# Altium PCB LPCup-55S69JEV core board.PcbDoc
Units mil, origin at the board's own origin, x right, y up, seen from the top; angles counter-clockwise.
Board outline 6000 x 4000 mil, 2 copper layers (Top Layer, Bottom Layer); 53 components, 52 nets, 231 pads, 94 vias.
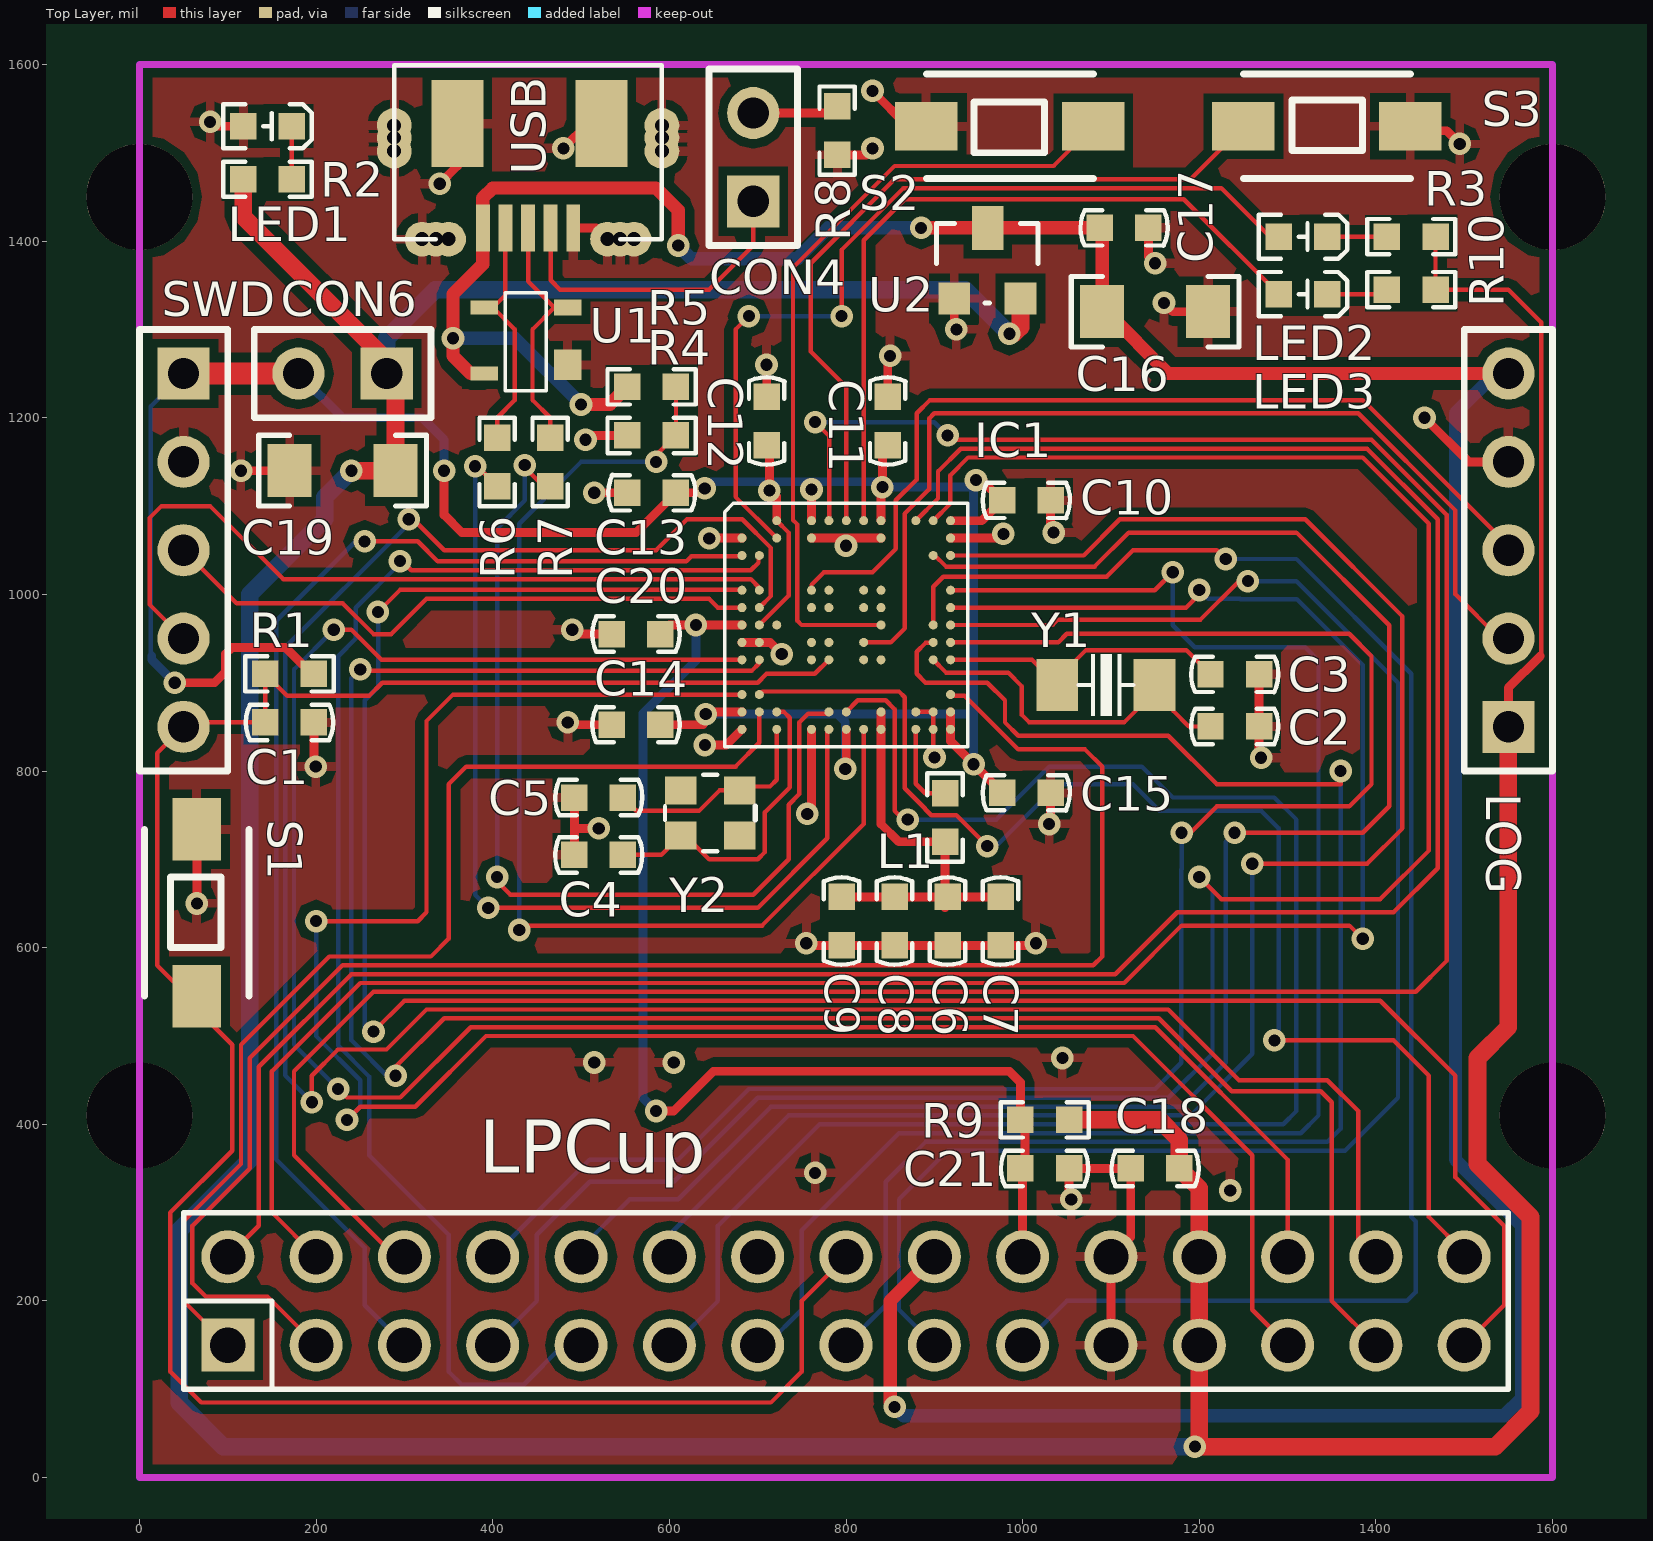
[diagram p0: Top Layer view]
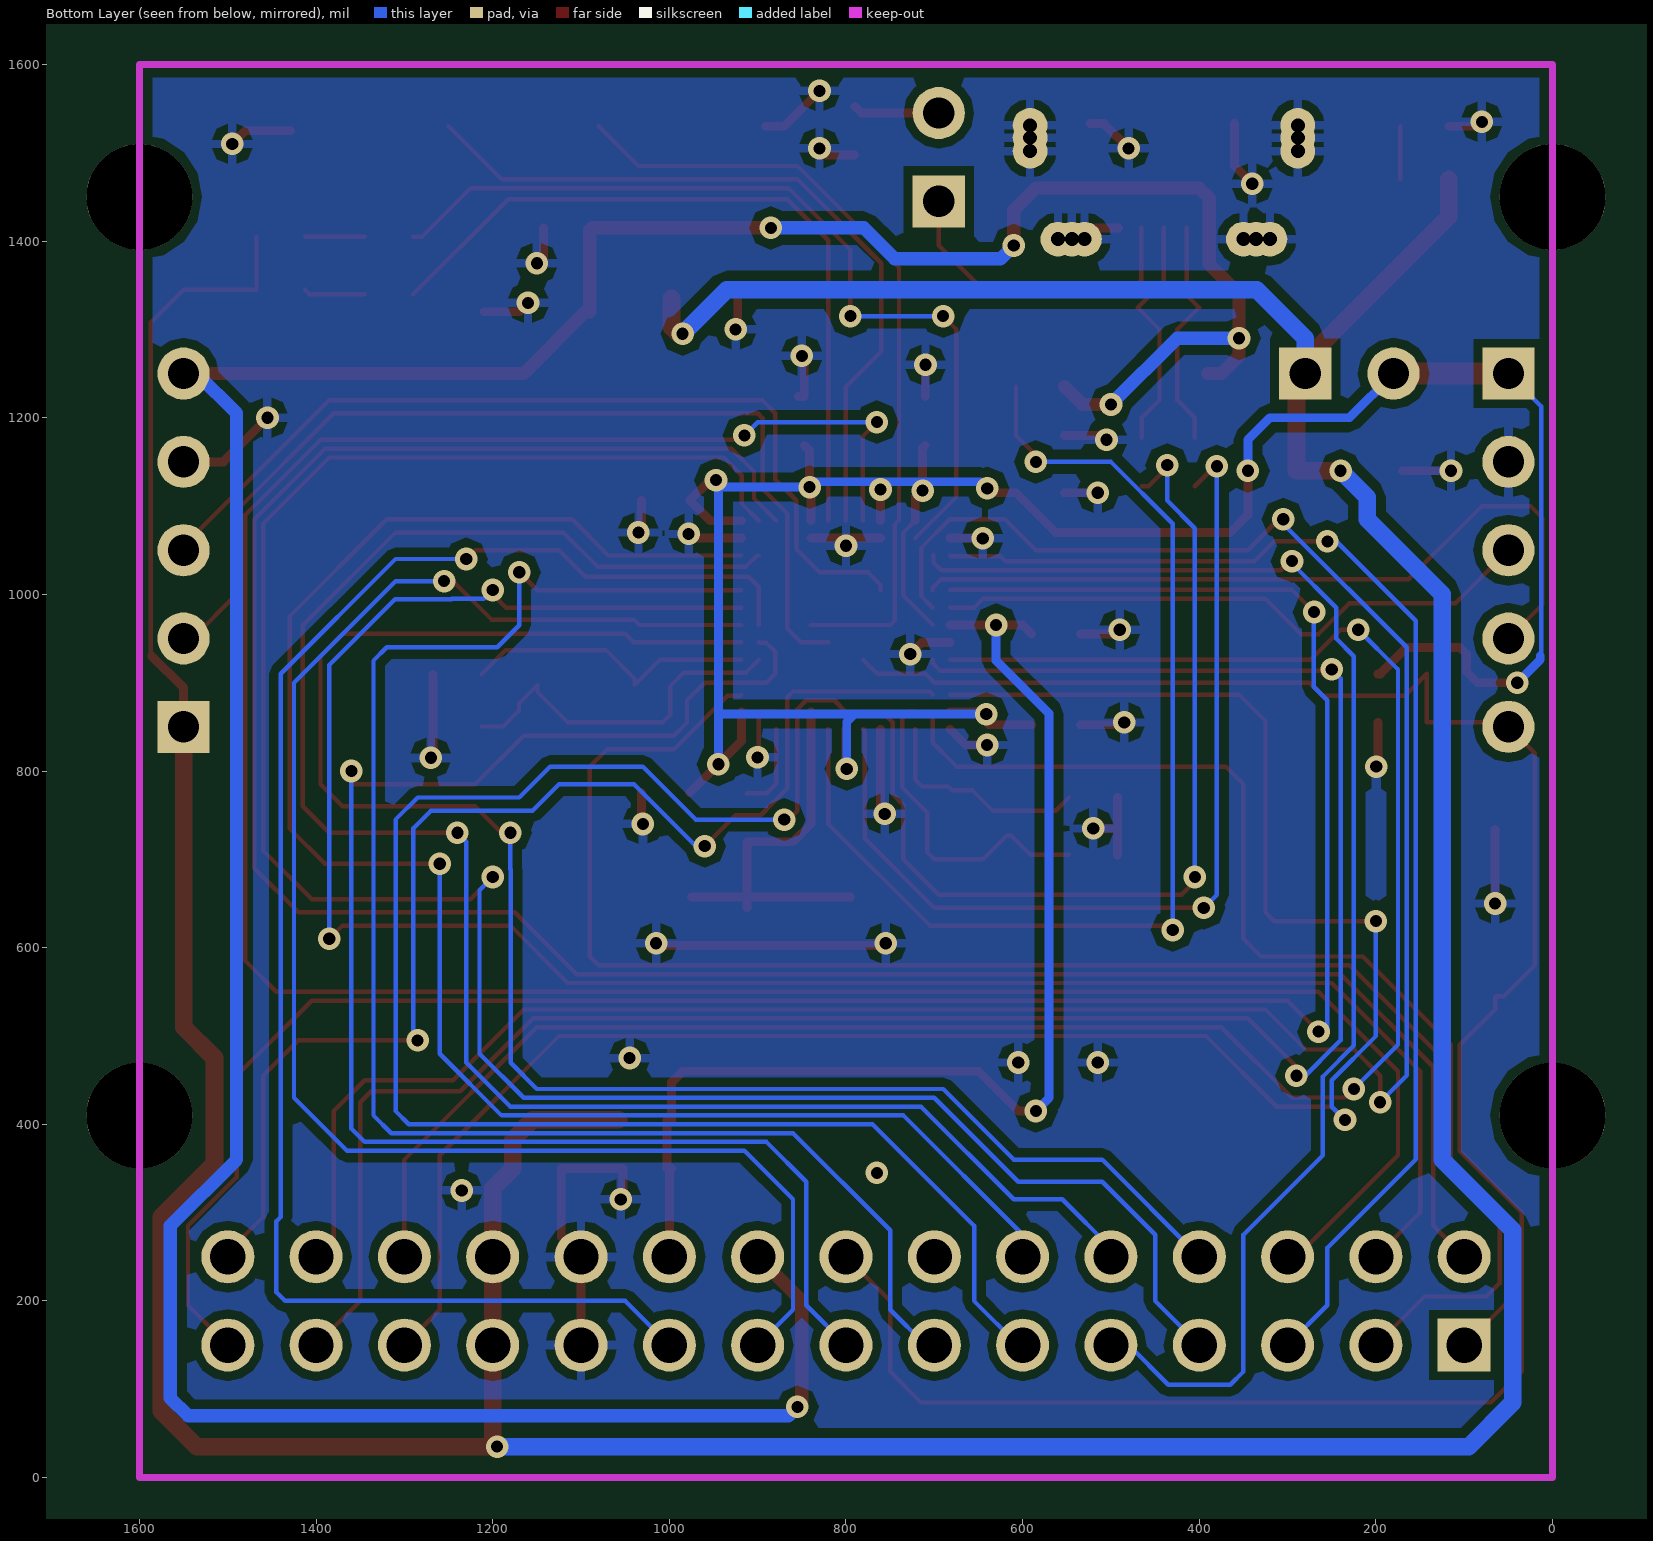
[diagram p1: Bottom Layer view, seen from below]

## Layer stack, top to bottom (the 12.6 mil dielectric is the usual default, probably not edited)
Top Solder: solder mask 0.4, Solder Resist, Dk 3.5
Top Layer: signal copper 1.4
Dielectric1: dielectric 12.6, FR-4, Dk 4.8
Bottom Layer: signal copper 1.4
Bottom Solder: solder mask 0.4, Solder Resist, Dk 3.5

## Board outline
-1716.54,-1216.54 4283.46,-1216.54 4283.46,2783.46 -1716.54,2783.46

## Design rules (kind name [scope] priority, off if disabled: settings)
Clearance [All] p1: gap=5
MinimumSolderMaskSliver [All] p1: minsoldermaskwidth=2
PolygonConnect [All] p1: connectstyle=Relief reliefconductorwidth=10 reliefentries=4 polygonreliefangle="90 Angle" airgapwidth=10
RoutingVias [All] p1: holewidth=13.78 width=25.59 viastyle="Through Hole" minholewidth=13.78 minwidth=25.59 maxholewidth=13.78 maxwidth=25.59
SilkToSolderMaskClearance SilkscreenOverComponentPads [IsPad] p1: minsilkscreentomaskgap=10 clearancetoexposedcopper=TRUE
SolderMaskExpansion [All] p1: expansion=3
Width [All] p1: maxlimit=50 minlimit=5 preferedwidth=8 minimp=50.000000 maximp=50.000000 favimp=50.000000
27 further rules are at their usual default settings.

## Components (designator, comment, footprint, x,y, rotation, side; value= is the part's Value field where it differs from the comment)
C1 "0.1uF" C0603 170,855 r180 top
C2 "0.1uF" C0603 1240.2,850.42 r180 top
C3 "0.1uF" C0603 1240.2,909.42 r180 top
C4 "0.1uF" C0603 520,705 r0 top
C5 "0.1uF" C0603 520,770 r0 top
C6 "2.2uF" C0603 915,630 r90 top
C7 "100nF" C0603 975,630 r90 top
C8 "47pF" C0603 855,630 r90 top
C9 "22uF" C0603 795,630 r90 top
C10 "0.1uF" C0603 1004.2,1106.42 r180 top
C11 "0.1uF" C0603 847.2,1196.42 r270 top
C12 "0.1uF" C0603 710.2,1196.42 r270 top
C13 "0.1uF" C0603 580,1115 r0 top
C14 "0.1uF" C0603 562.2,852.42 r0 top
C15 "0.1uF" C0603 1004.2,775.42 r180 top
C16 "10uF" C1206 1150,1320 r180 top
C17 "0.1uF" C0603 1115,1415 r180 top
C18 "0.1uF" C0603 1150,350 r0 top
C19 "10uF" C1206 230,1140 r0 top
C20 "0.1uF" C0603 562.2,955 r0 top
C21 "0.1uF" C0603 1025,350 r180 top
CON4 "SIP2" SIP2_2.54 695,1445 r90 top
CON6 "CON2" SIP2_2.54 280,1250 r180 top
IC1 "LPC55S69JEV98" VFBGA98_SIMPLE 682.2,1083.42 r0 top
L1 "48uH" L0603 912.2,747.42 r270 top
LED1 "LED" LED0603 145,1530 r0 top
LED2 "LED" LED0603 1317.5,1405 r0 top
LED3 "LED" LED0603 1317.5,1340 r0 top
LOG "SIP5" SIP5_2.54 1550,850 r90 top (schematic designator CON2)
LPCup "LPCUP" LPCUP 100,150 r90 top (schematic designator CON1)
R1 "10k" R0603 170,910 r0 top
R2 "4.7K" R0603 145,1470 r180 top
R3 "4.7K" R0603 1440,1405 r0 top
R4 "20K" R0603 580,1180 r0 top
R5 "10K" R0603 580,1235 r180 top
R6 "33R" R0603 405,1150 r90 top
R7 "33R" R0603 465,1150 r90 top
R8 "10K" R0603 790,1525 r90 top
R9 "0R" R0603 1025,405 r0 top
R10 "4.7K" R0603 1440,1345 r0 top
S1 "KEY" SW2P_4X6_SMD 65,545 r90 top
S2 "KEY" SW2P_4X6_SMD 1250,1530 r0 top
S3 "KEY" SW2P_4X6_SMD 1080,1530 r180 top
SWD "SIP5" SIP5_2.54 50,1250 r270 top (schematic designator CON5)
U1 "PRTR5V0U2X" SOT143B 485,1250 r180 top
U2 "HT7233" SOT23-3 960,1375 r270 top
USB "MicroUSB" MicroUSB 440,1415 r0 top (schematic designator CON3)
Y1 "32.768kHz" SMD3215_2P 1094.2,897.42 r180 top
Y2 "16.00MHz" SMD3225_4P 646.2,752.42 r0 top
? "Comment" FOOTPAD2#1 -170,590 r0 top
? "Comment" FOOTPAD2#2 165,590 r0 top
? "Comment" FOOTPAD2#3 1605,1220 r0 top
? "Comment" FOOTPAD2#4 135,1245 r0 top

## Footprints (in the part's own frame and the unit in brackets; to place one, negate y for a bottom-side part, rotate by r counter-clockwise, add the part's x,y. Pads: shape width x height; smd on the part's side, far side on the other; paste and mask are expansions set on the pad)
C0603 [mil]
  rect 30x30 smd: 1(27.5,0) 2(-27.5,0)
  silkscreen extent -49,-20 50,20
C1206 [mil]
  rect 50x60 smd: 1(60,0) 2(-60,0)
  silkscreen extent -95,-40 95,40
FOOTPAD2#1 [mil]
  round 120 hole 120 unplated: 0(170,-180)
FOOTPAD2#2 [mil]
  round 120 hole 120 unplated: 0(1435,-180)
FOOTPAD2#3 [mil]
  round 120 hole 120 unplated: 0(-5,230)
FOOTPAD2#4 [mil]
  round 120 hole 120 unplated: 0(-135,205)
L0603 [mil]
  rect 30x30 smd: 1(27.5,0) 2(-27.5,0)
  silkscreen extent -50,-20 50,20
LED0603 [mil]
  rect 30x30 smd: 1(27.5,0) 2(-27.5,0)
  silkscreen extent -50,-25 50,25
LPCUP [mil]
  rect 60x60 hole 40: 1(0,0)
  round 60 hole 40: 2(0,-100) 3(0,-200) 4(0,-300) 5(0,-400) 6(0,-500) 7(0,-600) 8(0,-700) 9(0,-800) 10(0,-900) 11(0,-1000) 12(0,-1100) 13(0,-1200) 14(0,-1300) 15(0,-1400) 16(100,0) 17(100,-100) 18(100,-200) 19(100,-300) 20(100,-400) 21(100,-500) 22(100,-600) 23(100,-700) 24(100,-800) 25(100,-900) 26(100,-1000) 27(100,-1100) 28(100,-1200) 29(100,-1300) 30(100,-1400)
  silkscreen extent -50,-1450 150,50
MicroUSB [mm]
  round 1 hole 0.4: 0(-3.85,2.206) 0(-3.85,2.591) 0(-3.85,2.946) 0(-3.048,-0.325) 0(-2.65,-0.325) 0(-2.286,-0.325) 0(2.286,-0.325) 0(2.65,-0.325) 0(3.048,-0.325) 0(3.85,2.206) 0(3.85,2.591) 0(3.85,2.946)
  rect 1.5x2.5 smd: 0(-2.032,2.997) 0(2.108,2.997)
  rect 0.4x1.35 smd: 1(-1.3,0) 2(-0.65,0) 3(0,0) 4(0.65,0) 5(1.3,0)
  silkscreen extent -3.85,-0.32 3.85,4.68
R0603 [mil]
  rect 30x30 smd: 1(27.5,0) 2(-27.5,0)
  silkscreen extent -50,-20 50,20
SIP2_2.54 [mm] "Connector; Header; 5 Position"
  rect 1.5x1.5 hole 0.9: 1(0,0)
  round 1.5 hole 0.9: 2(2.54,0)
  silkscreen extent -1.27,-1.27 3.81,1.27
SIP5_2.54 [mm] "Connector; Header; 5 Position"
  rect 1.5x1.5 hole 0.9: 1(0,0)
  round 1.5 hole 0.9: 2(2.54,0) 3(5.08,0) 4(7.62,0) 5(10.16,0)
  silkscreen extent -1.27,-1.27 11.43,1.27
SMD3215_2P [mm]
  rect 1.2x1.5 smd: 1(-1.4,0) 2(1.4,0)
  silkscreen extent -0.79,-0.89 0.79,0.89
SMD3225_4P [mm]
  rect 0.9x0.8 smd mask-0.051: 1(-0.85,-0.65) 2(0.85,-0.65) 3(0.85,0.65) 4(-0.85,0.65)
  silkscreen extent -1.3,-1.1 1.3,1.1
SOT23-3 [mil]
  rect 36x36 smd: 1(40,-37.5) 2(40,37.5)
  rect 50x36 smd: 3(-40,0.5)
  silkscreen extent -45,-58 45,58
SOT143B [mm]
  rect 0.8x0.88 smd: 1(0,-0.25)
  rect 0.8x0.45 smd: 2(0,-1.9)
  rect 0.8x0.4 smd: 3(2.4,-1.9) 4(2.4,0)
  silkscreen extent 0.63,-2.32 1.8,0.5
SW2P_4X6_SMD [mm]
  rect 1.8x1.4 smd: 1(0,0) 2(4.8,0)
  silkscreen extent 0,-1.5 4.8,1.5
VFBGA98_SIMPLE [mm]
  round 0.26 smd: A3(1,0) A5(2,0) A6(2.5,0) A7(3,0) A8(3.5,0) A9(4,0) A11(5,0) A12(5.5,0) A13(6,0) B1(0,-0.5) B3(1,-0.5) B5(2,-0.5) B9(4,-0.5) B13(6,-0.5) C1(0,-1) C2(0.5,-1) C12(5.5,-1) C13(6,-1) E1(0,-2) E2(0.5,-2) E5(2,-2) E6(2.5,-2) E8(3.5,-2) E9(4,-2) E13(6,-2) F1(0,-2.5) F2(0.5,-2.5) F5(2,-2.5) F6(2.5,-2.5) F8(3.5,-2.5) F9(4,-2.5) F13(6,-2.5) G1(0,-3) G2(0.5,-3) G3(1,-3) G9(4,-3) G12(5.5,-3) G13(6,-3) H1(0,-3.5) H2(0.5,-3.5) H5(2,-3.5) H6(2.5,-3.5) H8(3.5,-3.5) H12(5.5,-3.5) H13(6,-3.5) J1(0,-4) J2(0.5,-4) J5(2,-4) J6(2.5,-4) J8(3.5,-4) J9(4,-4) J12(5.5,-4) J13(6,-4) L1(0,-5) L2(0.5,-5) L13(6,-5) M1(0,-5.5) M2(0.5,-5.5) M3(1,-5.5) M6(2.5,-5.5) M7(3,-5.5) M9(4,-5.5) M11(5,-5.5) M12(5.5,-5.5) M13(6,-5.5) N1(0,-6) N3(1,-6) N5(2,-6) N6(2.5,-6) N7(3,-6) N8(3.5,-6) N9(4,-6) N11(5,-6) N12(5.5,-6) N13(6,-6)
  silkscreen extent -0.5,-6.5 6.5,0.5

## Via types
v1: diameter 25.59, hole 13.78, Top Layer to Bottom Layer, 94 vias

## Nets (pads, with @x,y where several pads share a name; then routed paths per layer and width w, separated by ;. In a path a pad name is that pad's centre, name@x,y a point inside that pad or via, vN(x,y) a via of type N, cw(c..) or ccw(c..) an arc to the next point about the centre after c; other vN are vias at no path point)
ADC0_0: IC1.J1 LPCup.28 | length 2319.8
  Top Layer w5: v1(220,960) 240,960 274.05,925.94 IC1.J1 ; v1(225,440) 234.7,430.3 295.3,430.3 375,510 1150,510 1300,360 LPCup.28
  Bottom Layer w5: v1(220,960) 175,915 175,490 v1(225,440)
ADC0_1: IC1.F2 LPCup.29 | length 2723
  Top Layer w5: v1(195.3,425) 195,425.3 195,455 224.7,484.7 279.7,484.7 325,530 1165,530 1245,450 1345,450 1380,415 1380,270 LPCup.29 ; v1(305,1085) 310,1085 345,1050 585,1050 620,1085 682.47,1085 715,1052.47 715,998.11 IC1.F2
  Bottom Layer w5: v1(195.3,425) 165,455.3 165,940 300,1075 300,1080 v1(305,1085)
ADC0_2: IC1.L2 LPCup.30 | length 1427.5
  Top Layer w5: IC1.L2 705.31,890 860,890 866.44,883.56 866.44,780.49 889.7,757.22 889.7,756.82 896.52,750 925,750 v1(960,715) ; v1(1285,495) 1420,495 1460,455 1460,295 1500,255 LPCup.30
  Bottom Layer w5: v1(960,715) 970,715 1040,785 1125,785 1155,755 1270,755 1290,735 1290,500 v1(1285,495)
ADC0_3: IC1.L1 LPCup.13 | length 2319.1
  Top Layer w5: v1(200,630) 315,630 325,640 325,856.57 355,886.57 IC1.L1 ; v1(235,405) 250,420 312.43,420 392.43,500 1125,500 1260,365 1260,190 LPCup.13
  Bottom Layer w5: v1(200,630) 200,500 250,450 250,420 v1(235,405)
ADC0_8: IC1.J2 LPCup.14 | length 2382.8
  Top Layer w5: v1(250,915) 251.67,913.33 693.11,913.33 701.89,922.11 IC1.J2 ; v1(290,455) 290,465 345,520 1154.14,520 1236.64,437.5 1337.5,437.5 1350,425 1350,200 LPCup.14
  Bottom Layer w5: v1(250,915) 240,905 240,495 285,450 v1(290,455)
ADC0_11: IC1.E1 LPCup.15 | length 2535.3
  Top Layer w5: v1(265,505) 300,540 1405,540 1490,455 1490,340 1545,285 1545,195 LPCup.15 ; v1(270,980) 295,1005 681.89,1005 IC1.E1
  Bottom Layer w5: v1(265,505) 255,505 255,880 270.3,895.3 270.3,979.7 v1(270,980)
GND: C1.2 C2.2 C3.2 C4.2 C5.2 C6.2 C7.2 C8.2 C9.2 C10.2 C11.2 C12.2 C13.2 C14.2 C15.2 C16.2 C17.2 C18.2 C19.2 C20.2 C21.2 IC1.B1 IC1.B5 IC1.B9 IC1.B13 IC1.H1 IC1.H2 IC1.M11 IC1.M12 IC1.N1 IC1.N5 IC1.N12 LED1.2 LOG.4 LPCup.11 LPCup.26 R4.2 R8.2 S1.2 S2.2 S3.2 SWD.2 U1.1 U2.1 USB.0 USB.5 | length 2425.9
  Top Layer w5: IC1.M11 IC1.M12 IC1.N12 898.74,824.89 904.2,819.42 v1(900.2,815.42)
  Top Layer w10: v1(65,650) S1.2 ; v1(80,1535) 85,1530 LED1.2 ; v1(115,1140) C19.2 ; C1.2 197.5,807.2 v1(199.7,805) ; v1(340,1465) 360,1485 USB.0@360,1533 ; v1(480,1505) 508,1533 USB.0@523,1533 ; v1(485,855) 487.57,852.42 C14.2 ; v1(490,960) 495,955 C20.2 ; USB.5 517.21,1415 USB.0@530,1402.21 ; C4.2 492.5,735 ; C5.2 492.5,735 ; v1(505,1175) 510,1180 R4.2 ; v1(515,1115) C13.2 ; v1(520,735) 492.5,735 ; v1(640.2,829.42) 664.42,829.42 IC1.N1 ; v1(645.2,1063.42) 645.52,1063.74 IC1.B1 ; IC1.H1 IC1.H2 714,945.63 v1(727.2,932.42) ; v1(710,1260) 710.2,1259.79 C12.2 ; v1(755,605) 757.5,602.5 C9.2 C8.2 C6.2 C7.2 1012.5,602.5 v1(1015,605) ; v1(756.2,751.42) 760.94,756.16 IC1.N5 ; IC1.B5 v1@800,1063.74 ; R8.2 822.5,1497.5 v1(830,1505) ; v1(800,1055) v1@800,1063.74 ; v1(830,1570) 870,1530 S3.2 ; IC1.B9 v1@800,1063.74 ; v1(850,1270) 847.2,1267.2 C11.2 C11.2@853.92,1223.92 ; IC1.B13 973.52,1063.74 v1(978.2,1068.42) ; U2.1 922.5,1302.5 v1(925,1300) ; v1(1030,740) 1031.7,741.7 C15.2 ; C10.2 1031.7,1066.7 v1(1035,1070) ; v1(1055,315) 1052.5,317.5 C21.2 C18.2 1122.5,272.5 LPCup.26 LPCup.11 ; C17.2 1142.5,1382.5 v1(1150,1375) ; v1(1160,1330) 1170,1320 C16.2 ; C3.2 C2.2 1267.7,817.29 v1(1270,815) ; S2.2@1428.98,1525 1480,1525 v1(1495,1510) ; v1(1455,1200) 1505,1150 LOG.4
  other v1: 1235,325 765,345 515,470 605,470 1045,475
HSSPI_MISO: IC1.G13 LPCup.9 | length 1839
  Top Layer w5: IC1.G13 1033.89,965.31 1040,971.42 1201.42,971.42 1245,1015 v1(1255,1015)
  Bottom Layer w5: LPCup.9 860,190 860,315 915,370 1365,370 1425,430 1425,900 1310,1015 v1(1255,1015)
HSSPI_MOSI: IC1.H12 LPCup.8 | length 1758.1
  Top Layer w5: IC1.H12 898.11,945 890,945 880,935 880,910 890,900 960,900 980,880 980,855 995,840 1165,840 1220,785 1360,785 v1(1360,800)
  Bottom Layer w5: LPCup.8 845,195 845,335 890,380 1345,380 1360,395 v1(1360,800)
HSSPI_SCK: IC1.G12 LPCup.10 | length 1831.7
  Top Layer w5: IC1.G12 898.74,1008.74 910,1020 1095,1020 1125,1050 1220,1050 v1(1230,1040)
  Bottom Layer w5: LPCup.10 1050,200 1435,200 1445,210 1445,290 1440,295 1440,448.75 1440,756.25 1440,910 1310,1040 v1(1230,1040)
HSSPI_SSEL: IC1.E13 LPCup.7 | length 1812
  Top Layer w5: IC1.E13 1149.68,1004.68 v1(1170,1025)
  Bottom Layer w5: LPCup.7 710,150 750,190 750,280 860,390 1315,390 1335,410 1335,925 1320,940 1195,940 1170,965 v1(1170,1025)
I2C1_SCL: IC1.C13 LPCup.21 | length 1985.6
  Top Layer w5: IC1.C13 1069.05,1044.05 1110,1085 1320,1085 1430,975 1430,735 1390,695 v1(1260,695)
  Bottom Layer w5: LPCup.21 600,275 735,410 1190,410 1260,480 v1(1260,695)
I2C1_SDA: IC1.C12 LPCup.20 | length 2064.5
  Top Layer w5: IC1.C12 900.58,1044.05 913.2,1031.44 1081.44,1031.44 1120,1070 1310,1070 1415,965 1415,760 1385,730 v1(1240,730)
  Bottom Layer w5: LPCup.20 500,260 555,315 610,315 715,420 1180,420 1230,470 1230,720 v1(1240,730)
MCU_RESET: C1.1 IC1.J6 LPCup.23 R1.2 S1.1 SWD.5 | length 2522.2
  Top Layer w5: IC1.J6 764.68,910 710,910 700,900 275,900 260,885 167.5,885 R1.2 C1.1 55,855 SWD.5 20,820 20,580 55,545 S1.1 65,530 105,490 105,370 35,300 35,120 70,85 715,85 750,120 750,200 LPCup.23
MCU_SWCLK: IC1.F1 SWD.3 | length 692.3
  Top Layer w5: SWD.3 110,990 230,990 265,955 285,955 325,995 645,995 655,985 IC1.F1
MCU_SWDIO: IC1.E2 SWD.4 | length 889.6
  Top Layer w5: SWD.4 11.5,988.5 11.5,1086.5 25,1100 80,1100 162.7,1017.3 692.2,1017.3 701.89,1007.62 IC1.E2
N16082712: IC1.N11 L1.2 | length 99.2
  Top Layer w5: IC1.N11 879.05,785.57 889.7,774.92 L1.2
N16082716: C6.1 C7.1 C8.1 C9.1 IC1.M9 IC1.N9 L1.1 | length 466.3
  Top Layer w10: C9.1 C8.1 C6.1 ; IC1.M9 IC1.N9 839.68,739.94 859.7,719.92 L1.1 C6.1@912.2,645.29 ; C6.1@912.2,660.29 C6.1 ; C7.1 C6.1
N16083730: C4.1 IC1.M3 Y2.1 | length 365.4
  Top Layer w5: C4.1 590.91,705 Y2.1 618.17,726.83 645,700 700,700 708.2,708.2 708.2,753.42 736.2,781.42 736.2,860.42 729.74,866.89 IC1.M3
N16083734: C5.1 IC1.N3 Y2.3 | length 252.2
  Top Layer w5: C5.1 562.5,755 591.68,755 591.92,754.77 633.56,754.77 656.81,778.02 Y2.3 684.08,782.42 713.94,782.42 721.57,790.05 IC1.N3
N16083761: C2.1 IC1.J12 Y1.1 | length 408.4
  Top Layer w5: IC1.J12 913.26,911.42 983.57,911.42 999.2,895.79 999.2,863.42 1007.2,855.42 1115.2,855.42 1149.32,889.54 Y1.1 1170.2,876.54 1170.2,868.42 1188.2,850.42 C2.1
N16083765: C3.1 IC1.J13 Y1.2 | length 337.9
  Top Layer w5: IC1.J13 1010.57,925.94 Y1.2 1039.09,904.31 1071.7,936.92 1185.2,936.92 C3.1
N16094991: R6.1 U1.3 USB.2 | length 261.9
  Top Layer w5: R6.1 405,1200 425,1220 425,1300 400.2,1324.8 414.41,1339.02 USB.2
N16095091: R7.1 U1.2 USB.3 | length 268.4
  Top Layer w5: USB.3 440,1354.61 469.8,1324.8 445,1300 445,1220 465,1200 R7.1
N16095095: CON4.1 USB.4 | length 363.9
  Top Layer w5: USB.4 465.59,1355.57 476.16,1345 645,1345 695,1395 CON4.1
N16095123: CON4.2 R8.1 | length 98.1
  Top Layer w10: CON4.2 782.5,1545 R8.1
N160852890: LED1.1 R2.2 | length 60
  Top Layer w5: R2.2 LED1.1
N161073140: LED2.1 R3.2 | length 67.5
  Top Layer w5: LED2.1 R3.2
N161283560: LED3.1 R10.2 | length 69.6
  Top Layer w5: LED3.1 1407.5,1340 R10.2
PIO0_05/ISP: IC1.A7 S2.1 | length 862.5
  Top Layer w5: IC1.A7 800.31,1234.68 760,1275 760,1375 855,1470 1190,1470 S2.1
PIO0_21/D3: IC1.A12 LPCup.4 | length 2505.8
  Top Layer w5: IC1.A12 918.2,1102.89 918.2,1135 938.2,1155 1385,1155 1460,1080 1460,710 1405,655 1225,655 v1(1200,680)
  Bottom Layer w5: LPCup.4 450,200 450,275 510,335 605,335 700,430 1165,430 1215,480 1215,665 v1(1200,680)
PIO0_25/D4: IC1.A11 LPCup.16 | length 2728.5
  Top Layer w5: LPCup.16 135,285 135,465 240,570 1105,570 1175,640 1420,640 1470,690 1470,1085 1390,1165 930,1165 904.2,1139.2 904.2,1108.57 IC1.A11
PIO0_28/D5: IC1.F13 LPCup.17 | length 2363.3
  Top Layer w5: LPCup.17 150,300 150,460 250,560 1115,560 1180,625 1370,625 v1(1385,610) ; IC1.F13 1185,985 1200,1000 v1(1200,1005)
  Bottom Layer w5: v1(1200,1005) 1210,995 1246.3,995 1246.59,994.7 1310.3,994.7 1385,920 v1(1385,610)
PIO1_08/D6: IC1.A6 LPCup.18 | length 3009.4
  Top Layer w5: LPCup.18 290,250 175,365 175,460 265,550 1445,550 1480,585 1480,1090 1395,1175 915,1175 v1(915,1180) ; v1(765,1195) 781.24,1178.76 781.24,1084.04 IC1.A6
  Bottom Layer w5: v1(765,1195) 900,1195 v1(915,1180)
PIO1_09/D2: IC1.C1 LPCup.3 | length 1457
  Top Layer w5: v1(255,1060) 315,1060 337.7,1037.3 619.17,1037.3 625,1043.13 681.28,1043.13 IC1.C1
  Bottom Layer w5: v1(255,1060) 245,1060 155,970 155,950 154.7,949.7 154.7,360.3 255,260 255,195 LPCup.3
PIO1_13/LEDG: IC1.B3 LED2.2 | length 1003.5
  Top Layer w5: v1(690,1315) 675,1300 675,1110.31 IC1.B3 ; v1(795,1315) 795,1390 865,1460 1225,1460 1280,1405 LED2.2
  Bottom Layer w5: v1(690,1315) v1(795,1315)
PIO1_18/WAKEUP: IC1.G9 S3.1 | length 905
  Top Layer w5: IC1.G9 749.68,965.31 745,970 745,1079.14 740,1084.14 740,1370 855,1485 1035,1485 S3.1
PIO1_19/D7: IC1.H13 LPCup.19 | length 2005
  Top Layer w5: IC1.H13 1040.31,945.63 1050,955.31 1369.68,955.31 1395,930 1395,785 1370,760 1220,760 1190,730 v1(1180,730)
  Bottom Layer w5: LPCup.19 510,360 610,360 690,440 1150,440 1179.7,469.7 1179.7,688.7 1180,689 v1(1180,730)
PIO1_20/D8: IC1.C2 LPCup.5 | length 1597.4
  Top Layer w5: v1(295,1037.6) 297.6,1037.6 307.89,1027.3 692.3,1027.3 700.94,1035.94 700.94,1045 IC1.C2
  Bottom Layer w5: v1(295,1037.6) 295,1035 245,985 245,950 225,930 225,489.14 260,454.14 260,365 350,275 350,120 365,105 435,105 480,150 LPCup.5
PIO1_21/D9: IC1.M7 LPCup.6 | length 1887.7
  Top Layer w5: IC1.M7 813.42,880 845,880 855,870 855,755 865,745 v1(870,745)
  Bottom Layer w5: LPCup.6 605,150 655,200 655,285 770,400 1295,400 1310,415 1310,745 1285,770 1170,770 1135,805 1030,805 970,745 v1(870,745)
PIO1_28/LEDB: IC1.A8 LED3.2 | length 851.3
  Top Layer w5: IC1.A8 820,1400.86 866.64,1447.5 1182.5,1447.5 LED3.2
UART0_RXD: IC1.H8 LOG.2 | length 1121.7
  Top Layer w5: IC1.H8 850.63,945.63 866.44,961.44 866.44,1091.44 894.2,1119.2 894.2,1199.2 900,1205 1380,1205 1490,1095 1490,1000 1540,950 LOG.2
UART0_TXD: IC1.E5 LOG.3 | length 1031.4
  Top Layer w5: IC1.E5 760.94,1010.94 775,1025 830,1025 856.44,1051.44 856.44,1106.44 880,1130 880,1205 895,1220 1385,1220 1550,1055 LOG.3
UART5_RXD: IC1.M2 LPCup.1 | length 1253.7
  Top Layer w5: LPCup.1 50,200 50,290 115,355 115,490 215,590 330,590 350,610 350,785 370,805 675,805 701.89,831.89 IC1.M2
UART5_TXD: IC1.L13 LPCup.2 | length 1883.9
  Top Layer w5: LPCup.2 145,205 75,205 60,220 60,285 125,350 125,475 230,580 1080,580 1090,590 1090,805 1070.57,824.42 995,824.42 934.42,885 920,885 IC1.L13
USB1_DM: IC1.N6 R6.2 | length 1081.1
  Top Layer w5: v1(380,1145) 382.5,1145 R6.2 ; v1(395,645) 700,645 778.91,723.91 778.91,845.48 IC1.N6
  Bottom Layer w5: v1(380,1145) 380,660 v1(395,645)
USB1_DP: IC1.M6 R7.2 | length 1072.9
  Top Layer w5: v1(405,680) 405,675 420,660 695,660 735.2,700.2 735.2,761.92 747.2,773.92 747.2,855 757.2,865 778.74,865 IC1.M6 ; v1@436.33,1143.67 457.5,1122.5 R7.2
  Bottom Layer w5: v1(405,680) 405,1075 436.33,1106.33 v1(436.33,1146.33)
USB1_VBUS: IC1.N8 R4.1 R5.2 | length 1285.2
  Top Layer w5: v1(430,620) 435,625 705,625 820,740 IC1.N8 ; v1(585,1150) 585,1157.5 R4.1 R5.2
  Bottom Layer w5: v1(430,620) 430,1080 500,1150 v1(585,1150)
VCC_3V3: C10.1 C11.1 C12.1 C13.1 C14.1 C15.1 CON6.2 IC1.A3 IC1.A5 IC1.A9 IC1.A13 IC1.G2 IC1.M1 IC1.M13 IC1.N7 IC1.N13 R1.1 SWD.1 | length 2990.5
  Top Layer w5: IC1.G2 735,998.42 735,1070 IC1.A3
  Top Layer w10: v1(40,900) 85,900 97.5,912.5 97.5,932.5 105,940 165,940 195,910 R1.1 ; v1(345,1140) 345,1090 365,1070 562.5,1070 C13.1 635,1115 v1(640,1120) ; C14.1 v1@638.2,852.42 ; v1@652.67,866.89 IC1.M1 ; C12.1 713.2,1165.92 v1(713.2,1117.42) ; IC1.A3 v1@721.57,1111.05 ; IC1.A5 v1(760.94,1118.68) ; v1(799.2,802.42) 800.2,802.42 800.31,802.53 IC1.N7 ; IC1.A9 839.68,1119.9 v1(841.2,1121.42) 841.2,1162.92 C11.1 ; IC1.M13 IC1.N13 918.42,833.7 v1(944.45,807.67) C15.1 ; IC1.A13 953.7,1083.42 C10.1 953.7,1129.42 v1(947.2,1129.42)
  Top Layer w25: SWD.1 CON6.2
  Bottom Layer w5: 15.77,931.87 12.97,934.66 12.97,1212.97 SWD.1
  Bottom Layer w10: 14,930.1 14,926 v1(40,900) ; CON6.2 230,1200 320,1200 345,1175 v1(345,1140) ; v1(640,1120) 647.42,1127.42 835.2,1127.42 v1(841.2,1121.42) v1@940.2,1121.42 ; v1(641.2,864.42) 790.57,864.42 ; v1(799.2,802.42) 799.2,855.79 790.57,864.42 ; v1(944.45,807.67) 944.45,865 ; v1@944.45,1126.67 944.45,865 ; 790.57,864.42 943.88,864.42 944.45,865
VCC_IN: C16.1 C17.1 LOG.5 LPCup.24 R5.1 U1.4 U2.3 USB.1 | length 3972.8
  Top Layer w15: U1.4 375,1250 355,1270 v1(355,1290) 355,1340 388.82,1373.82 USB.1 388.82,1448.82 400,1460 585,1460 610,1435 v1(610,1395) ; v1(500,1215) 532.5,1215 R5.1 ; v1(855,80) 850,85 850,200 LPCup.24 ; v1(885,1415) U2.3 C17.1 1090,1412.5 C16.1 1095,1320 1165,1250 v1(1550,1250)
  Bottom Layer w15: v1(355,1290) 425,1290 v1(500,1215) ; v1(610,1395) 625,1380 745,1380 780,1415 v1(885,1415) ; v1(855,80) 865,70 1545,70 1565,90 1565,285 1490,360 1490,1205 1535,1250 v1(1550,1250)
VCC_OUT: C18.1 C19.1 CON6.1 LOG.1 LPCup.12 LPCup.27 R2.1 R3.1 R9.1 R10.1 U2.2 | length 5961.8
  Top Layer w5: R3.1 R10.1 1550,1345 1587.03,1307.97 1587.03,931.13 1586,930.1
  Top Layer w10: LOG.1 1550,894.1 1586,930.1
  Top Layer w20: R2.1 117.5,1427.5 280,1265 CON6.1 290,1240 C19.1 v1(240,1140) ; v1(985,1295) 990,1295 997.5,1302.5 U2.2 ; R9.1@1057.5,405 1155,405 1177.5,382.5 C18.1 1200,327.5 LPCup.27 LPCup.12 1200,40 v1(1195,35) 1535,35 1575,75 1575,295 1515,355 1515,475 1550,510 LOG.1
  Bottom Layer w20: v1(240,1140) 210,1110 210,1085 125,1000 125,360 45,280 45,85 95,35 v1(1195,35) ; CON6.1 280,1290 335,1345 935,1345 v1(985,1295)
VREF: C20.1 C21.1 IC1.G1 LPCup.25 R9.2 | length 1316.5
  Top Layer w10: v1(585,415) 605,415 650,460 985,460 997.5,447.5 R9.2 ; C20.1 600.02,965.31 v1(630,965.31) IC1.G1 ; C21.1 C21.1@1000,347.5 ; LPCup.25 C21.1@1000,347.5 ; R9.2@1002.5,405 1002.5,350 C21.1@1000,347.5
  Bottom Layer w10: v1(585,415) 570,430 570,865 630,925 v1(630,965.31)
pads on no net: ?.0 IC1.E6 IC1.E8 IC1.E9 IC1.F5 IC1.F6 IC1.F8 IC1.F9 IC1.G3 IC1.H5 IC1.H6 IC1.J5 IC1.J8 IC1.J9 LPCup.22 Y2.2 Y2.4

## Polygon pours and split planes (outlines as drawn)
GND on Bottom Layer "Top Layer-No Net" (solid, remove dead copper, pour order 4): -1.08,1603.23 1598.92,1603.23 1598.92,3.23 -1.08,3.23 -1.08,1598.23
GND on Top Layer "Top Layer-No Net" (solid, remove dead copper, pour order 3): -8.4,1602.78 1591.6,1602.78 1591.6,2.78 -8.4,2.78 -8.4,1597.78

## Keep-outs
Keep-Out Layer:
  lines w7.87: 0,0 1600,0 ; 0,1600 1600,1600
  lines w8: 0,0 0,1600 ; 1600,0 1600,1600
